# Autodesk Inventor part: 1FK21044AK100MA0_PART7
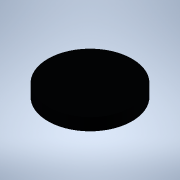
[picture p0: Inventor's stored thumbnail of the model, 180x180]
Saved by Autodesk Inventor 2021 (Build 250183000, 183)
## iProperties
Created: 2025-04
Part Number: 1FK21044AK100MA0_PART7
Material: Generic
Catalog Web Link: www.3dfindit.com
Description: -Servo synchronous motor
Document SubType Name: Modeling
Designer: psAdmin
Mass: 0.299142 g
Surface Area: 3.8585 cm^2
Volume: 0.299142 cm^3
Density: 1 g/cm^3
Appearance: PSOLRGB-38-46-56
Category: PARTsolutions
Title: 1FK21044AK100MA0_PART7
Author: Cadenas PARTsolutions
Comments: Servo synchronous motor
Sending System: PARTsolutions
Preprocessor: ST-DEVELOPER v19.3
PSOL_IDENT_0: {$CADENAS_DATA/23d-libs/siemens_ag/_cat_/5e/d8/1fk21044ak100ma0.prj},213 {VTYP=3D},{NB=1FK21044AK100
PSOL_IDENT_1: MA0_PART7},{LINA=1FK21044AK100MA0_PART7},{NN=1FK21044AK100MA0_PART7},{NOPRJ=TRUE},{DATE=19.08.2025 1
PSOL_IDENT_2: 4:00:41},{GEOMDATE=30.07.2025 02:00:53},{VERSION=},{LINEID=10},{WBVAR=},{WBNUMERIC=}  {NB=1FK21044AK
PSOL_IDENT_3: 100MA0_PART7},{LINA=1FK21044AK100MA0_PART7},{KT=DUMMY},{PREVIEW=../../../_pool_/cb/72/p_d211_xx_0043
PSOL_IDENT_4: 4j.png},{DESCSHORT=SIMOTICS S-1FK2 HD, SINAMICS S210 3AC 400V-480V, 0.95 Nm, 6000 rpm},{DESCLONG=SIM
PSOL_IDENT_5: OTICS S-1FK2 HD servo motor M0=1.27 Nm; PN = 0.6 kW at nN=6000 rpm (380-480 V); PN = 0.4 kW at nN=30
PSOL_IDENT_6: 00 rpm (200-240 V); with holding brake; degree of protection IP64; cylindrical shaft D19x40mm; absol
PSOL_IDENT_7: ute encoder 22-bit + 12-bit multiturn (encoder AM22DQC); with OCC interface; plug size M17, rotatabl
PSOL_IDENT_8: e; SIMOTICS S-1FK2 servomotorfor a wide range of uses in industrial environments. SIMOTICS S‑1FK2 se
PSOL_IDENT_9: rvomotors are compact synchronous motors with a high dynamic performance that set themselves apart a
PSOL_IDENT_10: s a result of their high power density, degree of protection and overload capability. The motors are
PSOL_IDENT_11: available in two variants: as High Dynamic variant (highest dynamic performance as a result of the
PSOL_IDENT_12: low intrinsic moment of inertia for applications demanding a high dynamic performance with low moved
PSOL_IDENT_13: masses) - and as Compact variant (precise and stable closed-loop control for medium up to large mov
PSOL_IDENT_14: ed masses as a result of a medium intrinsic moment of inertia). SIMOTICSS‑1FK2 servomotors fully exp
PSOL_IDENT_15: loit their strengths in a system with the SINAMICSS210 frequency converter and simple connection usi
PSOL_IDENT_16: ng the one cable connection (OCC). Advantages include the short control and positioning times, fast
PSOL_IDENT_17: and precise correction of disturbing quantities as well as stable control with a high dynamic perfor
PSOL_IDENT_18: mance. The servo motors can be configured to address a wide range of requirements. For example with
PSOL_IDENT_19: and without holding brake, IP64 or IP65 degree of protection, singleturn or multiturn absolute encod
PSOL_IDENT_20: ers - to name just a few. Further, the servomotors are available in different shaft heights extendin
PSOL_IDENT_21: g from 20 to 100. A shaft sealing ring is available to achieve an IP65 degree of protection and for
PSOL_IDENT_22: subsequent mounting at the motor or as spare part. SIMOTICS - the optimum motor for each and every m
PSOL_IDENT_23: otion control application.},{INTNO=804766910005},{SUPPLIERALTNO=1FK2104-4AK10-0MA0},{MANUID=1FK21044
PSOL_IDENT_24: AK100MA0},{MANUNAME=Siemens},{MANUTYPEDESC=Synchronous motor 1FK2-HD 1,27 Nm},{AAU732=SIMOTICS},{AAO
PSOL_IDENT_25: 057=S-1FK2},{AAU734=SIMOTICS S-1FK2 HD servo motor M0=1.27 Nm; PN = 0.6 kW at nN=6000 rpm (380-480 V
PSOL_IDENT_26: ); PN = 0.4 kW at nN=3000 rpm (200-240 V); with holding brake; degree of protection IP64; cylindrica
PSOL_IDENT_27: l shaft D19x40mm; absolute encoder 22-bit + 12-bit multiturn (encoder AM22DQC); with OCC interface;
PSOL_IDENT_28: plug size M17, rotatable;},{AAW338=Synchronous motor 1FK2-HD 1,27 Nm},{AAO742=SIMOTICS},{AAO663=4042
PSOL_IDENT_29: 948691076},{NOCUPEROU=1},{PRICEQUANTITY=1},{QUANTITYMIN=1},{QUANTITYINT=1},{CTN=85015100},{COO=DE},{
PSOL_IDENT_30: AAO676=1FK2104-4AK10-0MA0},{AAO677=Siemens AG},{ORDERUNIT=C62},{CONTENTUNIT=C62}
NB: 1FK21044AK100MA0_PART7
NT: Servo synchronous motor
NBSYN: $MANUID._PART7
LINA: 1FK21044AK100MA0_PART7
CATALOG: SIEMENS
PREVIEW: ../../../_pool_/cb/72/p_d211_xx_00434j.png
DESCSHORT: SIMOTICS S-1FK2 HD, SINAMICS S210 3AC 400V-480V, 0.95 Nm, 6000 rpm
DESCLONG: SIMOTICS S-1FK2 HD servo motor M0=1.27 Nm; PN = 0.6 kW at nN=6000 rpm (380-480 V); PN = 0.4 kW at nN=3000 rpm (200-240 V); with holding brake; degree of protect
INTNO: 804766910005
SUPPLIERALTNO: 1FK2104-4AK10-0MA0
MANUID: 1FK21044AK100MA0
MANUNAME: Siemens
MANUTYPEDESC: Synchronous motor 1FK2-HD 1,27 Nm
AAU732: SIMOTICS
AAO057: S-1FK2
AAU734: SIMOTICS S-1FK2 HD servo motor M0=1.27 Nm; PN = 0.6 kW at nN=6000 rpm (380-480 V); PN = 0.4 kW at nN=3000 rpm (200-240 V); with holding brake; degree of protect
AAW338: Synchronous motor 1FK2-HD 1,27 Nm
AAO742: SIMOTICS
AAO663: 4042948691076.0
NOCUPEROU: 1
PRICEQUANTITY: 1
QUANTITYMIN: 1
QUANTITYINT: 1
CTN: 85015100
COO: DE
ARTICLENO: 1FK21044AK100MA0_PART7
BOMINFO: 1FK21044AK100MA0_PART7
CREATOR: CADENAS GmbH
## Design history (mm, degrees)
feature "2025_04_17_15_35_41_0937"
body "Solid1"
